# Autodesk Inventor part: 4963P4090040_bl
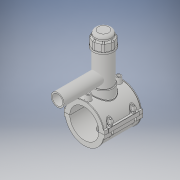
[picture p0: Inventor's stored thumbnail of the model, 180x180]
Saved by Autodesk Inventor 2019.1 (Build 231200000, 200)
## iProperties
Created: 2017-07
Part Number: 4963P4090040_bl
Material: Generic
Document SubType Name: Modeling
Designer: KIM
Density: 1 g/cm^3
Appearance: Default
Author: KIM
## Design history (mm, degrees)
derived "4963P4.ipt"
feature "Solid1::4963P4.ipt" dims "ScaleForDerivedMember" = 10
feature "Solid2::4963P4.ipt" dims "ScaleForDerivedMember" = 10
feature "Solid3::4963P4.ipt" dims "ScaleForDerivedMember" = 10
tag "TaggingFeature1"
body "Solid1"
body "Solid2"
body "Solid3"
other parameters: "d2" = 126 [user parameter], "d3" = 22.5 [user parameter], "d4" = 118 [user parameter], "d5" = 0 [user parameter], "d6" = 0.1 [user parameter], "d8" = 0 [user parameter], "d19" = 6 [user parameter], "d20" = 6 [user parameter], "d21" = 70.8 [user parameter], "d23" = 0 [user parameter], "d24" = 35.4 [user parameter], "d26" = 0 [user parameter], "d27" = 3 [user parameter], "d28" = 3 [user parameter], "d29" = 3 [user parameter], "d31" = 6 [user parameter], "d32" = 0 [user parameter], "d33" = 0 [user parameter], "d34" = 0.6 [user parameter], "d40" = 60.84 [user parameter], "d41" = 63 [user parameter], "d43" = 0 [user parameter], "d45" = 0 [user parameter], "d47" = 129.3 [user parameter], "d70" = 15 [user parameter], "d72" = 0 [user parameter], "d73" = 6 [user parameter], "d75" = 5 [user parameter], "d76" = 0 [user parameter], "d77" = 4.5 [user parameter], "d78" = 75 [user parameter], "d79" = 15 [user parameter], "d80" = 47.2 [user parameter], "d82" = 5 deg [user parameter], "d84" = 4 [user parameter], "d85" = 14 [user parameter], "d86" = 0 [user parameter], "d87" = 3 [user parameter], "d88" = 0 [user parameter], "d89" = 1 [user parameter], "d90" = 1 [user parameter], "d91" = 94.4 [user parameter], "d92" = 0 [user parameter], "d93" = 0.5 [user parameter], "d94" = 47.36842 [user parameter], "d96" = 119.34 [user parameter], "d97" = 2.36 [user parameter], "d98" = 0 [user parameter], "d102" = 0.9 [user parameter], "d120" = 140 deg [user parameter], "d121" = 24.228 [user parameter], "d122" = 20 deg [user parameter], "d123" = 234 [user parameter], "d124" = 70.2 [user parameter], "d126" = 0 [user parameter], "d143" = 92.7 [user parameter], "d145" = 20.76923 [user parameter], "d149" = 1.35 [user parameter], "d150" = 22.84615 [user parameter], "d153" = 118 [user parameter], "d154" = 0 [user parameter], "d156" = 58.5 [user parameter], "d157" = 160 deg [user parameter], "d159" = 5.4 [user parameter], "d161" = 1.35 [user parameter], "d162" = 70.8 [user parameter], "d163" = 0 [user parameter], "d164" = 45 [user parameter], "d167" = 9 [user parameter], "d168" = 57.07317 [user parameter], "d170" = 3.75 [user parameter], "d172" = 0 [user parameter], "d173" = 1 [user parameter], "d175" = 45 [user parameter], "d176" = 20 deg [user parameter], "d177" = 6.3 [user parameter], "d178" = 27 [user parameter], "d180" = 0 [user parameter], "d183" = 10.8 [user parameter], "d184" = 5.04 [user parameter], "d185" = 38.35 [user parameter], "d186" = 38.35 [user parameter], "d187" = 58.5 [user parameter], "d188" = 8.1 [user parameter], "d189" = 6.3 [user parameter], "d190" = 0 [user parameter], "d191" = 87.75 [user parameter], "d193" = 8 [user parameter], "d194" = 4.13 [user parameter], "d195" = 90 deg [user parameter], "d197" = 0 [user parameter], "d199" = 0 [user parameter], "d200" = 13.5 [user parameter], "d202" = 0 [user parameter], "d203" = 177 [user parameter], "d204" = 59.85 [user parameter], "d205" = 44.1 [user parameter], "d206" = 53.55 [user parameter], "d207" = 132.75 [user parameter], "d208" = 138.06 [user parameter], "d209" = 164.61 [user parameter], "d210" = 54.18 [user parameter], "d211" = 63 [user parameter], "d212" = 50.4 [user parameter], "d213" = 36 [user parameter], "d216" = 0 [user parameter], "d217" = 9 [user parameter], "d218" = 9 [user parameter], "d219" = 1.8 [user parameter], "d224" = 0 [user parameter], "d227" = 32 [user parameter], "d228" = 142 [user parameter], "d230" = 5.4 [user parameter], "B_" = 126 [user parameter], "L_" = 118 [user parameter], "d_t" = 6 [user parameter], "H_2" = 177 [user parameter], "H_" = 142 [user parameter], "d1" = 117 [user parameter], "d148" = 1.35 [user parameter]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
